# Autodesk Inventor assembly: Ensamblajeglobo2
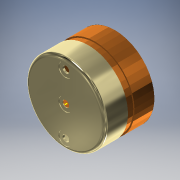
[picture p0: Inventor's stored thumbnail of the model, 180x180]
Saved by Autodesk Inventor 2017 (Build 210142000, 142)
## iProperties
Part Number: Ensamblajeglobo2
Material: Genérico
Document SubType Name: Assembly
Designer: Yavhee
Author: Yavhee
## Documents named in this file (3)
- C:\Users\Yavhee\Desktop\globoinventor\Ensamblajeglobo2.iam
- C:\Users\Yavhee\Desktop\globoinventor\piezadeabajo120mm.ipt
- C:\Users\Yavhee\Desktop\globoinventor\piezadegasconrespectoapiezabaja.ipt
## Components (2 placed, 2 different names)
1. piezadeabajo120mm:1 — De rotación:1
2. piezadegasconrespectoapiezabaja:1 — De rotación:1
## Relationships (1: RevoluteJoint 1)
- De rotación:1 [RevoluteJoint]: piezadeabajo120mm:1 ↔ piezadegasconrespectoapiezabaja:1
